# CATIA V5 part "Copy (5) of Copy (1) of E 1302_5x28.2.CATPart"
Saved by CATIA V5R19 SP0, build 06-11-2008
Part number: Copy (5) of Copy (1) of E 1302_5x28.2
Nomenclature: E 1302_5x28
Source: Unknown
Description: PART-E 1302_5x28-DESC
Bounding box of the stored display mesh (mm): x -2.5 to 2.5, y -2.5 to 2.5, z 0 to 28
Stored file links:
  C:\Users\jsmid\Desktop\DP_Smidak_Forma LEGO\Copy (5) of Copy (1) of E 1302_5x28.2.CATPart
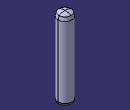
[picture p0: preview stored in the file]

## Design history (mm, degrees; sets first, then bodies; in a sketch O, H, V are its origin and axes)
Body1 "E 1302_5x28" (main body)
  Solid1: solid without history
